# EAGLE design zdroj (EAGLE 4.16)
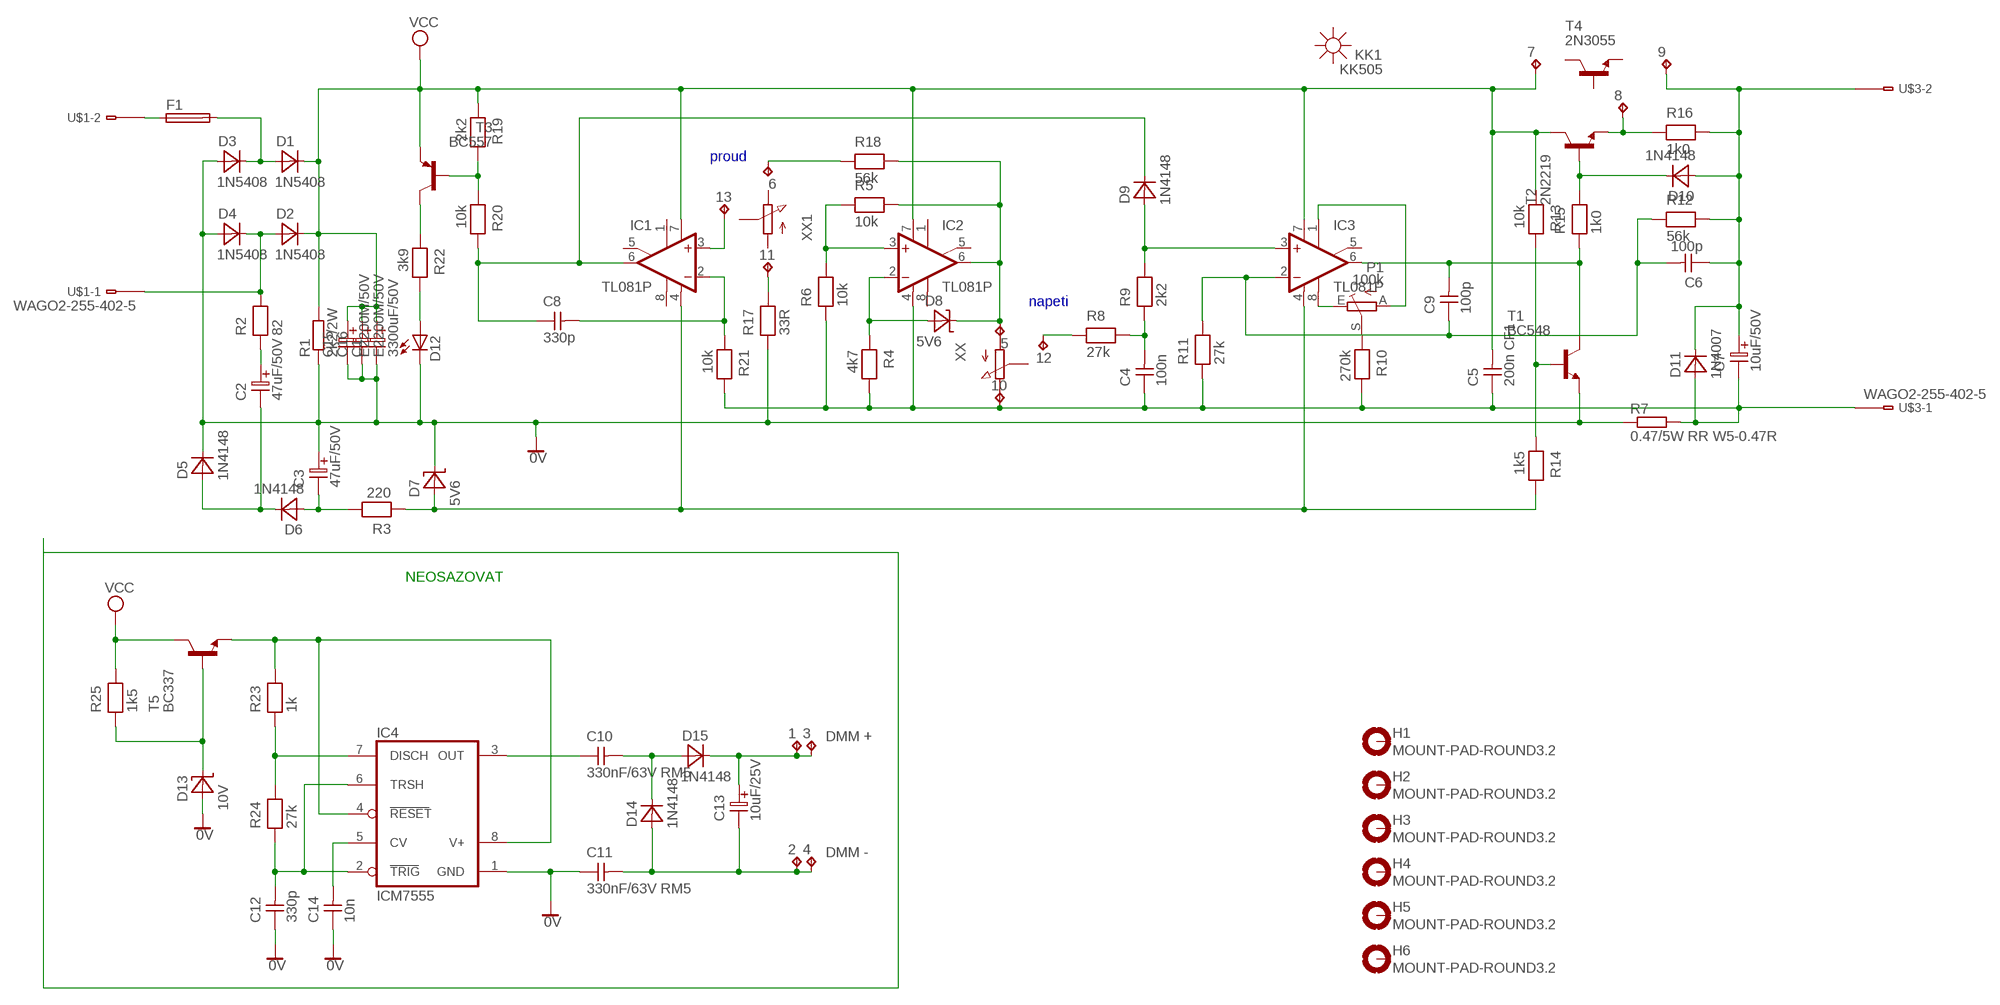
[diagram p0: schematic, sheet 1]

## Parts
1  TPPAD1-13Y  [P1-13Y]
2  TPPAD1-13Y  [P1-13Y]
3  TPPAD1-13Y  [P1-13Y]
4  TPPAD1-13Y  [P1-13Y]
5  TPPAD1-13Y  [P1-13Y]
6  TPPAD1-13Y  [P1-13Y]
7  TPPAD1-13Y  [P1-13Y]
8  TPPAD1-13Y  [P1-13Y]
9  TPPAD1-13Y  [P1-13Y]
10  TPPAD1-13Y  [P1-13Y]
11  TPPAD1-13Y  [P1-13Y]
12  TPPAD1-13Y  [P1-13Y]
13  TPPAD1-13Y  [P1-13Y]
C1  3300uF/50V  ELC-45L  [E-45L]
C2  47uF/50V  ELC-5  [ES-5]
C3  47uF/50V  ELC-5  [ES-5]
C4  100n  CAPNP-5  [C-5]
C5  200n CF1  CAPNP-5  [C-5]
C6  100p  CAPNP-5  [C-5]
C7  10uF/50V  ELC-2,5L  [ES-2,5L]
C8  330p  CAPNP-5  [C-5]
C9  100p  CAPNP-5  [C-5]
C10  330nF/63V RM5  CAPNP-5  [C-5]
C11  330nF/63V RM5  CAPNP-5  [C-5]
C12  330p  CAPNP-5  [C-5]
C13  10uF/25V  ELC-2,5L  [ES-2,5L]
C14  10n  CAPNP-5  [C-5]
C15  E2200M/50V  ELC-7,5  [ES-7,5]
C16  E2200M/50V  ELC-7,5  [ES-7,5]
D1  1N5408  DIODE-12,5  [D-12,5]
D2  1N5408  DIODE-12,5  [D-12,5]
D3  1N5408  DIODE-12,5  [D-12,5]
D4  1N5408  DIODE-12,5  [D-12,5]
D5  1N4148  DIODE-7,5  [D-7,5]
D6  1N4148  DIODE-7,5  [D-7,5]
D7  5V6  ZDIO-7,5  [D-7,5]
D8  5V6  ZDIO-7,5  [D-7,5]
D9  1N4148  DIODE-7,5  [D-7,5]
D10  1N4148  DIODE-7,5  [D-7,5]
D11  1N4007  DIODE-7,5  [D-7,5]
D12  LED3MM  [LED3MM]
D13  10V  ZDIO-7,5  [D-7,5]
D14  1N4148  DIODE-7,5  [D-7,5]
D15  1N4148  DIODE-7,5  [D-7,5]
F1  SH22,5A  [SH22,5A]
H1  MOUNT-PAD-ROUND3.2  [3,2-PAD]
H2  MOUNT-PAD-ROUND3.2  [3,2-PAD]
H3  MOUNT-PAD-ROUND3.2  [3,2-PAD]
H4  MOUNT-PAD-ROUND3.2  [3,2-PAD]
H5  MOUNT-PAD-ROUND3.2  [3,2-PAD]
H6  MOUNT-PAD-ROUND3.2  [3,2-PAD]
IC1  TL081P  [DIL08]
IC2  TL081P  [DIL08]
IC3  TL081P  [DIL08]
IC4  ICM7555  [DIL08]
KK1  KK505  [KK505]
P1  100k  TRIM_EU-CA6V  [CA6V]
R1  2k2/2W  R-EU_0414/15  [0414/15]
R2  82  RESEU-7,5  [R-7,5]
R3  220  RESEU-7,5  [R-7,5]
R4  4k7  RESEU-7,5  [R-7,5]
R5  10k  RESEU-7,5  [R-7,5]
R6  10k  RESEU-7,5  [R-7,5]
R7  0.47/5W RR W5-0.47R  R-EU_0922/22  [0922/22]
R8  27k  RESEU-7,5  [R-7,5]
R9  2k2  RESEU-7,5  [R-7,5]
R10  270k  RESEU-7,5  [R-7,5]
R11  27k  RESEU-7,5  [R-7,5]
R12  56k  RESEU-7,5  [R-7,5]
R13  10k  RESEU-7,5  [R-7,5]
R14  1k5  RESEU-7,5  [R-7,5]
R15  1k0  RESEU-7,5  [R-7,5]
R16  1k0  RESEU-7,5  [R-7,5]
R17  33R  RESEU-7,5  [R-7,5]
R18  56k  RESEU-7,5  [R-7,5]
R19  2k2  RESEU-7,5  [R-7,5]
R20  10k  RESEU-7,5  [R-7,5]
R21  10k  RESEU-7,5  [R-7,5]
R22  3k9  RESEU-7,5  [R-7,5]
R23  1k  RESEU-7,5  [R-7,5]
R24  27k  RESEU-7,5  [R-7,5]
R25  1k5  RESEU-7,5  [R-7,5]
T1  BC548  [TO92-EBC]
T2  2N2219  [TO5]
T3  BC557  [TO92-EBC]
T4  2N3055  2N2219  [TO5]
T5  BC337  BC338  [TO92-EBC]
U$1  WAGO2-255-402-5  [255-402-5]
U$3  WAGO2-255-402-5  [255-402-5]
XX  PC25  [PC25]
XX1  PC25  [PC25]

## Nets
0V: C1.2 C3.1 C11.1 C12.1 C14.1 C15.2 C16.2 D3.1(A) D4.1(A) D5.2(K) D7.2(K) D12.K(C) D13.1(A) IC4.1(GND) R1.1 R7.1 R17.1 T1.E
N$1: D2.1(A) D4.2(K) R2.2 U$1.B1(-1:B1)
N$2: D1.1(A) D3.2(K) F1.2
N$4: D13.2(K) R25.1 T5.B
N$5: F1.1 U$1.B2(-2:B1)
N$6: C3.2 D6.1(A) R3.2
N$7: D7.1(A) IC1.4(V-) IC3.4(V-) R3.1 R14.2
N$8: C2.2 D5.1(A) D6.2(K)
N$9: D12.A R22.2
N$10: C2.1 R2.1
N$11: C14.2 IC4.5(CV)
N$12: R22.1 T3.C
N$13: R19.2 R20.1 T3.B
N$14: C8.1 D9.2(K) IC1.6(OUT) R20.2
N$15: C8.2 IC1.2(-IN) R21.1
N$16: 8.1(TP) R16.1 T2.1(E)
N$17: 13.1(TP) IC1.3(+IN)
N$18: 6.1(TP) R18.1
N$19: 5.1(TP) D8.2(K) IC2.6(OUT) R5.2 R18.2
N$20: 11.1(TP) R17.2
N$21: D8.1(A) IC2.2(-IN) R4.1
N$22: IC2.3(+IN) R5.1 R6.2
N$23: 12.1(TP) R8.1
N$24: C4.2 R8.2 R9.1
N$25: D9.1(A) IC3.3(+IN) R9.2
N$26: C6.2 C9.1 IC3.2(-IN) R11.2 R12.1
N$27: IC3.1(ON1) P1.A
N$28: IC3.8(OPT) P1.E
N$29: P1.S R10.1
N$30: C9.2 IC3.6(OUT) R15.1 T1.C
N$31: R13.2 R14.1 T1.B
N$32: D10.2(K) R15.2 T2.2(B)
N$33: C10.1 IC4.3(OUT)
N$35: 9.1(TP) C6.1 C7.1 D10.1(A) D11.2(K) R12.2 R16.2 U$3.B2(-2:B1)
N$36: IC4.4(RESET) IC4.8(V+) R23.2 T5.E
N$37: IC4.7(DISCH) R23.1 R24.2
N$38: C12.2 IC4.2(TRIG) IC4.6(TRSH) R24.1
N$39: 1.1(TP) 3.1(TP) C13.1 D15.2(K)
N$40: 2.1(TP) 4.1(TP) C11.2 C13.2 D14.1(A)
N$41: C10.2 D14.2(K) D15.1(A)
N$43: 10.1(TP) C4.1 C5.1 C7.2 D11.1(A) IC2.4(V-) R4.2 R6.1 R7.2 R10.2 R11.1 R21.2 U$3.B1(-1:B1)
VCC: 7.1(TP) C1.1 C5.2 C15.1 C16.1 D1.2(K) D2.2(K) IC1.7(V+) IC2.7(V+) IC3.7(V+) R1.2 R13.1 R19.1 R25.2 T2.3(C) T3.E T5.C
Unconnected: H1.B3,2(MOUNT) H2.B3,2(MOUNT) H3.B3,2(MOUNT) H4.B3,2(MOUNT) H5.B3,2(MOUNT) H6.B3,2(MOUNT) IC1.1(ON1) IC1.5(ON2) IC1.8(OPT) IC2.1(ON1) IC2.5(ON2) IC2.8(OPT) IC3.5(ON2) T4.1(E) T4.2(B) T4.3(C) U$1.A1(-1:A1) U$1.A2(-2:A1) U$3.A1(-1:A1) U$3.A2(-2:A1) XX1.A XX1.E XX1.S XX.A XX.E XX.S

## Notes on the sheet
- proud
- napeti
- NEOSAZOVAT
- DMM +
- DMM -

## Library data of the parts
1-13 = testpad:TP
C1 = discrete:ELC-45L
C2 C3 = discrete:ELC-5
C4-C6 C8-C12 C14 = discrete:CAPNP-5
C7 C13 = discrete:ELC-2,5L
C15 C16 = discrete:ELC-7,5
D1-D4 = discrete:DIODE-12,5
D5 D6 D9-D11 D14 D15 = discrete:DIODE-7,5
D7 D8 D13 = discrete:ZDIO-7,5
D12 = led:LED: LED
F1 = fuse:SH22,5A: FUSE HOLDER
H1-H6 = holes:MOUNT-PAD-ROUND: MOUNTING PAD, round
IC1-IC3 = linear:TL081: OP AMP
IC4 = maxim:ICM7555: TIMER
KK1 = heatsink:KK505: HEATSINK
P1 = pot:TRIM_EU-: POTENTIOMETER
R1 R7 = rcl:R-EU_: RESISTOR, European symbol
R2-R6 R8-R25 = discrete:RESEU-7,5
T1 = transistor-npn:BC548*: NPN Transistor
T2 T4 = transistor-npn:2N2219: NPN Transistor
T3 = transistor-pnp:BC557*: PNP Transistror
T5 = transistor-npn:BC338*: NPN Transistor
U$1 U$3 = con-wago:WAGO2-: WAGO Cage Clamp
XX XX1 = pot-vitrohm:PC25: VITROHM POTENTIOMETER

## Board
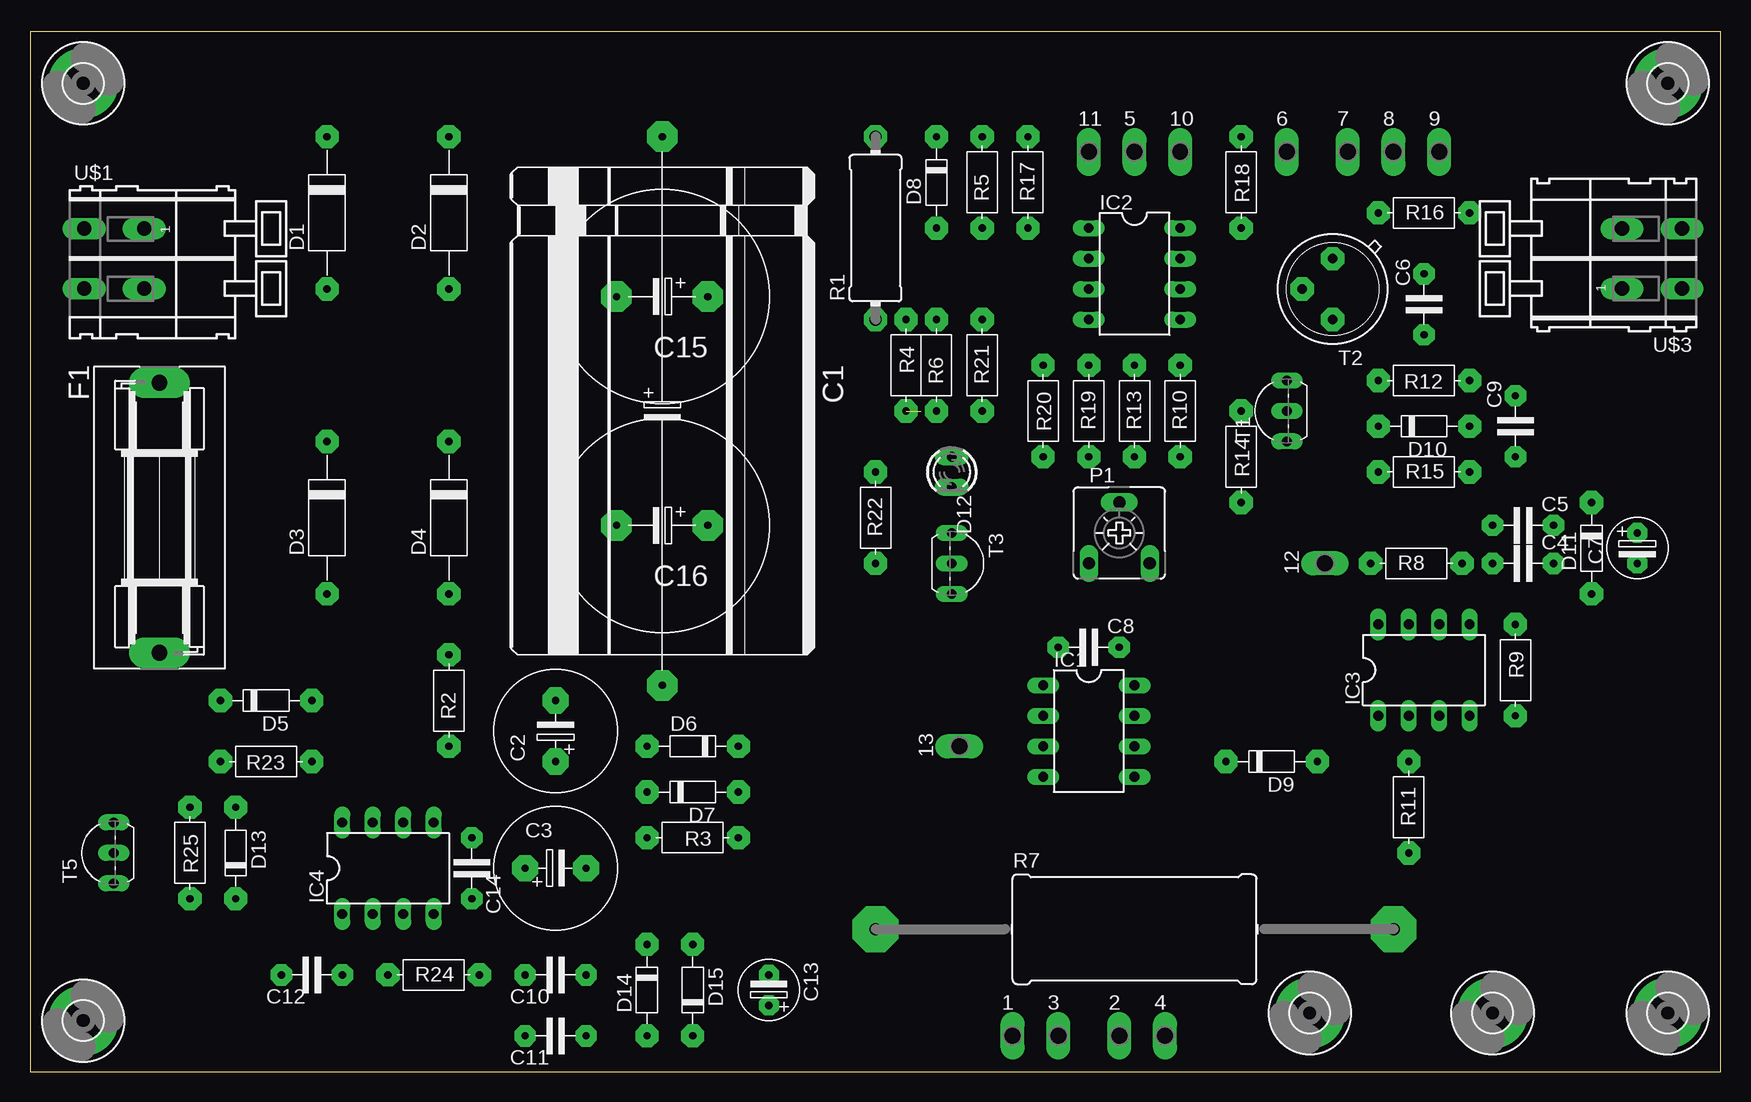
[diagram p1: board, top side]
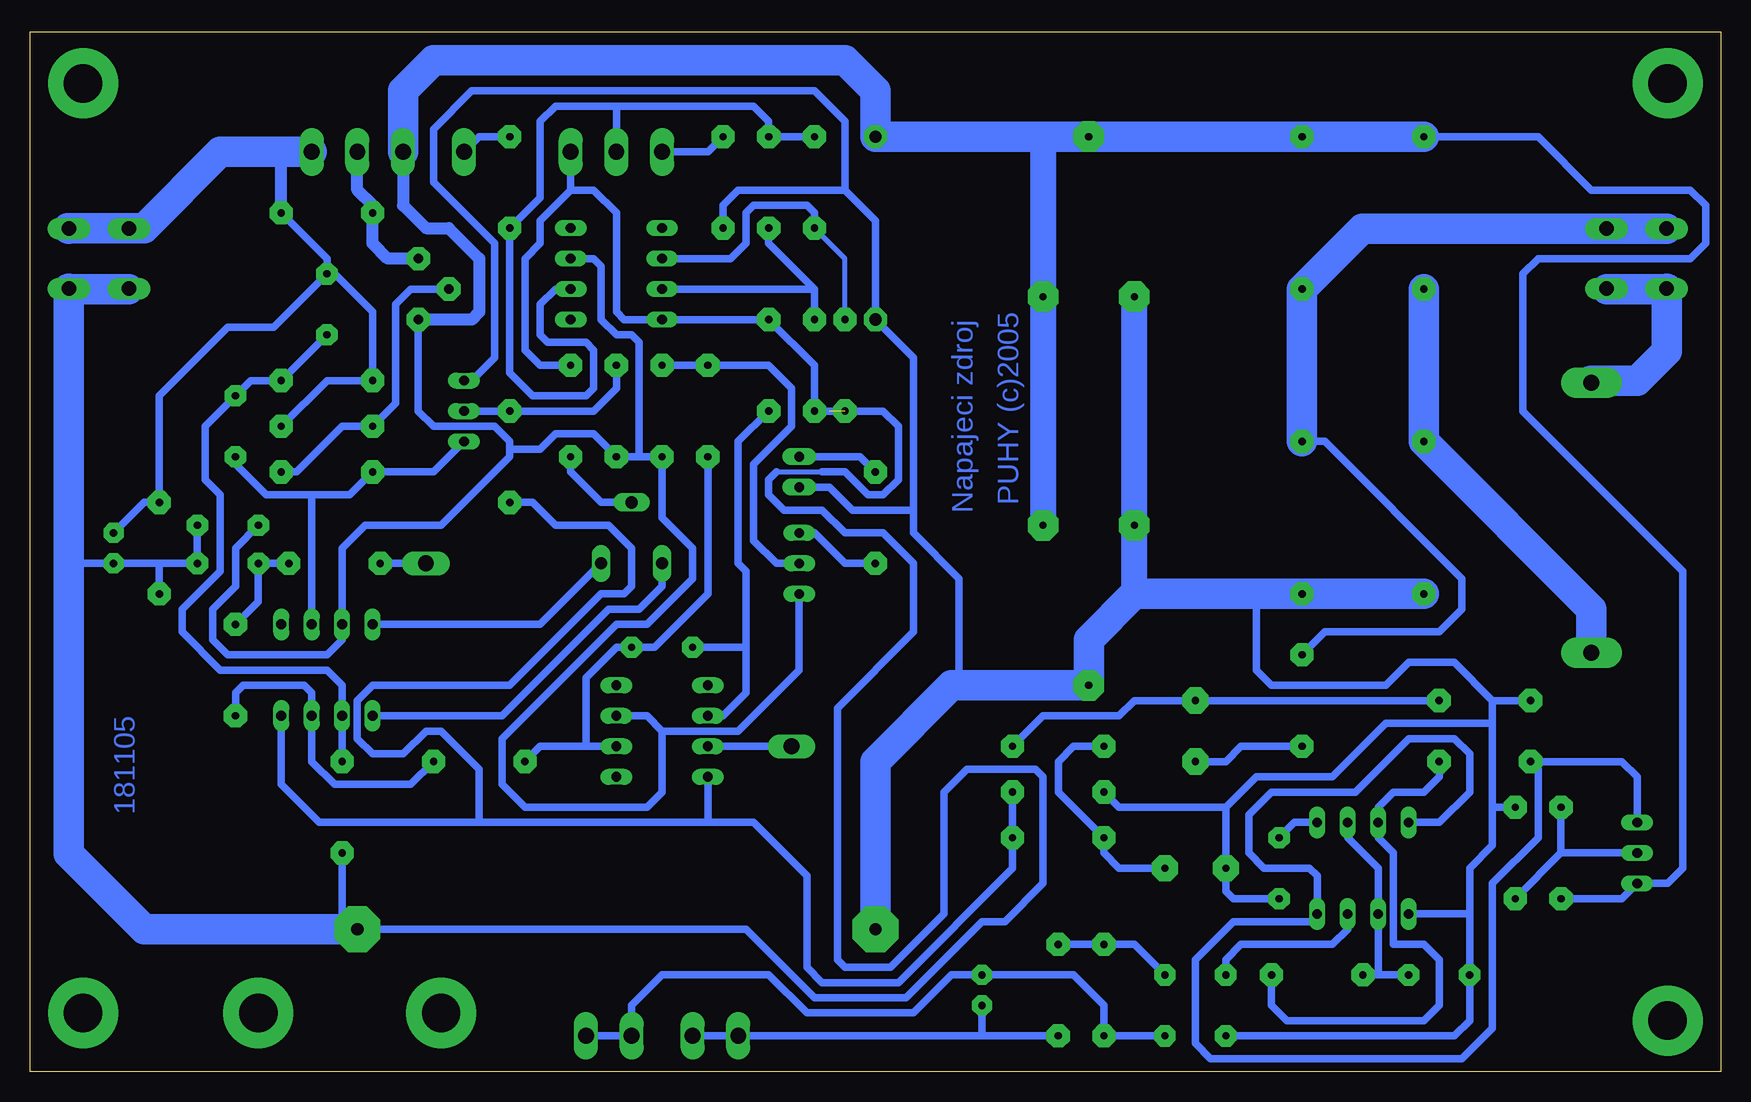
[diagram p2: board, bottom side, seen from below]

Size 140.95 x 86.67 mm. Coordinates in mm from the lower left corner, seen from the top.
Outline: 0,0 140.95,0 140.95,86.67 0,86.67 0,0
Copper layers (1*16): Top 0.035mm / dielectric 1.5mm / Bottom 0.035mm
Design rules "default": minimum track width 10mil, minimum drill 24mil, track to track 8mil, track to pad 8mil, pad to pad 8mil, via to via 8mil, smd to smd 8mil, copper to edge 40mil, drill to drill 8mil, minimum pad ring 10mil, minimum via ring 8mil, stop-mask expansion 4mil, vias tented up to drill 0mil, thermal gap 10mil

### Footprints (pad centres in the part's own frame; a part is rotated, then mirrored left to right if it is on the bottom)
P1-13Y = drill 1.321 pad 1.905 long: 1 0,0
E-45L = drill 0.61 pad 2.54 octagon: 1 0,0; 2 45.72,0
ES-5 = drill 0.61 pad 2.184 octagon: 1 -2.54,0; 2 2.54,0
C-5 = drill 0.61 pad 1.778 octagon: 1 -2.54,0; 2 2.54,0
ES-2,5L = drill 0.61 pad 1.676 octagon: 1 0,0; 2 2.54,0
ES-7,5 = drill 0.61 pad 2.54 octagon: 1 -3.81,0; 2 3.81,0
D-12,5 = drill 0.61 pad 1.93 octagon: 1 -6.35,0; 2 6.35,0
D-7,5 = drill 0.61 pad 1.93 octagon: 1 -3.81,0; 2 3.81,0
LED3MM = drill 0.813 pad 1.422 long: A -1.27,0; K 1.27,0
SH22,5A = drill 1.321 pad 2.54 long: 1 -11.252,0; 2 11.252,0
3,2-PAD = drill 3.2 pad 5.842 round: B3,2 0,0
DIL08 = drill 0.813 long: 1 -3.81,-3.81; 2 -1.27,-3.81; 3 1.27,-3.81; 4 3.81,-3.81; 5 3.81,3.81; 6 1.27,3.81; 7 -1.27,3.81; 8 -3.81,3.81
CA6V = drill 1.016 long: A -2.54,-2.54; E 2.54,-2.54; S 0,2.54
0414/15 = drill 1.016 pad 1.93 octagon: 1 -7.62,0; 2 7.62,0
R-7,5 = drill 0.61 pad 1.93 octagon: 1 -3.81,0; 2 3.81,0
0922/22 = drill 1.016 pad 3.81 octagon: 1 -21.59,0; 2 21.59,0
TO92-EBC = drill 0.813 long: B 0,-1.27; C -2.54,-1.27; E 2.54,-1.27
TO5 = drill 0.813 pad 1.93 octagon: 1 0,-2.54; 2 2.54,0; 3 0,2.54
255-402-5 = drill 1.2 long: A1 -2.5,0; A2 2.5,0; B1 -2.5,-5; B2 2.5,-5
PC25 = smd 2.2 x 0.8: 4 0,1.65 | smd 0.9 x 1.4: A -1.35,-1.9; E 1.35,-1.9; S 0,-1.9

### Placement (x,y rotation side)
1  81.91,3.01 0 top
2  90.8,3.01 0 top
3  85.72,3.01 0 top
4  94.61,3.01 0 top
5  92.07,76.67 0 top
6  104.77,76.67 0 top
7  109.85,76.67 0 top
8  113.66,76.67 0 top
9  117.47,76.67 0 top
10  95.88,76.67 0 top
11  88.26,76.67 0 top
12  107.94,42.38 90 top
13  77.47,27.14 90 top
C1  52.7,77.94 270 top
C2  43.81,28.41 90 top
C3  43.81,16.98 0 top
C4  124.46,42.38 180 top
C5  124.46,45.56 180 top
C6  116.2,63.97 270 top
C7  133.98,44.92 270 top
C8  88.26,35.39 180 top
C9  123.82,53.81 270 top
C10  43.81,8.09 0 top
C11  43.81,3.01 0 top
C12  23.49,8.09 0 top
C13  61.59,5.55 90 top
C14  36.83,16.98 90 top
C15  52.7,64.61 180 top
C16  52.7,45.56 180 top
D1  24.76,71.59 90 top
D2  34.92,71.59 90 top
D3  24.76,46.19 90 top
D4  34.92,46.19 90 top
D5  19.68,30.95 180 top
D6  55.24,27.14 0 top
D7  55.24,23.33 180 top
D8  75.56,74.13 90 top
D9  103.5,25.87 180 top
D10  116.2,53.81 180 top
D11  130.17,43.65 90 top
D12  76.83,50 270 top
D13  17.14,18.25 270 top
D14  51.43,6.82 90 top
D15  55.24,6.82 270 top
F1  10.79,46.19 270 top
H1  4.44,82.39 0 top
H2  4.44,4.28 0 top
H3  121.91,4.91 0 top
H4  136.52,4.91 0 top
H5  106.68,4.91 0 top
H6  136.52,82.39 0 top
IC1  88.26,28.41 270 top
IC2  92.07,66.51 270 top
IC3  116.2,33.49 0 top
IC4  29.84,16.98 0 top
KK1  not placed on the board
P1  90.8,44.92 0 top
R1  70.48,70.32 90 top
R2  34.92,30.95 90 top
R3  55.24,19.52 180 top
R4  73.02,58.89 270 top
R5  79.37,74.13 90 top
R6  75.56,58.89 90 top
R7  92.07,11.9 0 top
R8  115.56,42.38 0 top
R9  123.82,33.49 270 top
R10  95.88,55.08 90 top
R11  114.93,22.06 90 top
R12  116.2,57.62 180 top
R13  92.07,55.08 90 top
R14  100.96,51.27 270 top
R15  116.2,50 0 top
R16  116.2,71.59 0 top
R17  83.18,74.13 90 top
R18  100.96,74.13 270 top
R19  88.26,55.08 90 top
R20  84.45,55.08 270 top
R21  79.37,58.89 90 top
R22  70.48,46.19 90 top
R23  19.68,25.87 180 top
R24  33.65,8.09 0 top
R25  13.33,18.25 270 top
T1  103.5,55.08 90 top
T2  108.58,65.24 180 top
T3  78.1,42.38 270 top
T4  not placed on the board
T5  5.71,18.25 90 top
U$1  9.52,67.78 270 top
U$3  132.71,67.78 90 top
XX  not placed on the board
XX1  not placed on the board

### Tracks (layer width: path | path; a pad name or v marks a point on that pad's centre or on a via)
0V
  Bottom 0.61: 20.95,13.17 C12.1 20.95,4.28 22.22,3.01 C11.1 | 20.95,13.17 IC4.1 | 41.27,22.06 38.73,24.6 32.38,24.6 27.94,29.04 19.04,29.04 | 41.27,22.06 50.16,22.06 D7.2 | 20.95,13.17 20.95,16.98 19.04,18.89 19.04,22.06 | 19.04,22.06 D13.1 | 19.04,22.06 19.04,29.04 | C14.1 40.63,14.44 41.27,15.07 C3.1 41.27,22.06 | 73.02,73.5 81.91,73.5 83.18,72.23 R17.1 | 67.31,46.83 67.31,44.92 63.49,41.11 63.49,32.22 | 67.31,46.83 67.31,59.53 R1.1 70.48,70.95 73.02,73.5 | T1.E 104.13,57.62 102.23,59.53 102.23,69.05 107.31,74.13 107.31,78.58 104.13,81.75 75.56,81.75 73.02,79.21 73.02,73.5 | 67.31,46.83 72.38,46.83 74.29,48.73 D12.K | 38.73,39.84 38.73,33.49 37.46,32.22 27.94,32.22 26.03,34.12 22.22,34.12 19.04,30.95 | 19.04,29.04 19.04,30.95 | 19.04,30.95 D5.2
  Bottom 2.184: C15.2 C16.2 48.89,39.84
  Bottom 2.54: R7.1 70.48,25.87 64.13,32.22 63.49,32.22 62.23,32.22 | D3.1 D4.1 38.73,39.84 48.89,39.84 52.7,36.03 C1.2 | C1.2 52.7,33.49 | C1.2 62.23,32.22 | 62.23,32.22 62.86,32.22
N$1
  Bottom 0.61: R2.2 33.02,36.67 23.49,36.67 21.59,38.57 21.59,41.11 33.02,52.54 D4.2
  Bottom 2.54: U$1.B1 29.88,70.28 D2.1 D4.2
N$2
  Bottom 2.54: D1.1 D3.2 10.79,38.57 F1.2
N$3
  Bottom 2.54: 132.71,65.24 137.79,65.24
N$4
  Bottom 0.61: 13.33,18.25 D13.2 | 13.33,18.25 R25.1 | T5.B 13.33,18.25
N$5
  Bottom 2.54: U$1.B2 4.52,60.08 6.98,57.62 10.79,57.62 F1.1
N$6
  Bottom 0.61: D6.1 53.97,27.14 55.24,25.87 55.24,23.33 R3.2 51.43,18.25 50.16,16.98 C3.2
N$7
  Bottom 0.61: IC3.4 120.01,23.96 116.84,20.79 103.5,20.79 | 84.45,20.79 80.64,20.79 76.19,16.34 76.19,8.73 74.92,7.46 68.58,7.46 59.05,16.98 R3.1 D7.1 | 84.45,20.79 103.5,20.79 | 84.45,20.79 IC1.4 | 103.5,20.79 103.5,25.24 106.68,28.41 107.94,28.41 109.85,26.5 112.39,26.5 113.66,27.78 113.66,30.95 112.39,32.22 100.96,32.22 93.34,39.84 91.44,39.84 90.8,40.47 90.8,43.65 92.71,45.56 97.15,45.56 99.06,47.46 R14.2
N$8
  Bottom 0.61: D5.1 C2.2 48.89,30.95 50.16,29.68 56.51,29.68 D6.2
N$9
  Bottom 0.61: R22.2 71.75,51.27 D12.A
N$10
  Bottom 0.61: R2.1 40,27.14 41.27,25.87 C2.1
N$11
  Bottom 0.61: C14.2 35.55,20.79 IC4.5
N$12
  Bottom 0.61: R22.1 73.02,42.38 75.56,44.92 T3.C
N$13
  Bottom 0.61: T3.B 78.73,42.38 80.64,44.28 80.64,50.64 77.47,53.81 77.47,56.98 79.37,58.89 R20.1 R19.2
N$14
  Bottom 0.61: D9.2 98.42,27.14 94.61,27.14 | IC1.6 94.61,27.14 | 94.61,27.14 94.61,32.86 92.07,35.39 C8.1 88.9,35.39 84.45,39.84 R20.2
N$15
  Bottom 0.61: IC1.2 83.18,29.68 81.28,31.58 81.28,35.39 | 81.28,35.39 C8.2 | R21.1 81.91,52.54 81.91,42.38 81.28,41.75 81.28,35.39
N$16
  Bottom 1.016: T2.1 111.12,67.78 112.39,69.05 R16.1 112.39,72.23 113.66,73.5 8.1
N$17
  Bottom 0.61: 13.1 IC1.3
N$18
  Bottom 0.61: R18.1 103.5,77.94 6.1
N$19
  Bottom 0.61: D8.2 R5.2 79.37,79.21 80.64,80.48 92.07,80.48 | 92.07,80.48 97.15,80.48 98.42,79.21 98.42,72.86 R18.2 100.96,58.26 99.06,56.35 94.61,56.35 93.97,56.98 93.97,60.16 94.61,60.8 97.78,60.8 98.42,61.43 98.42,63.97 97.15,65.24 IC2.6 | 92.07,80.48 5.1
N$20
  Bottom 0.61: 11.1 84.45,76.67 R17.2
N$21
  Bottom 0.406: R4.1 73.02,67.78 D8.1
  Bottom 0.61: D8.1 75.56,71.59 76.19,72.23 80.64,72.23 81.28,71.59 81.28,69.05 82.55,67.78 IC2.2
N$22
  Bottom 0.61: R6.2 75.56,65.24 | 75.56,65.24 IC2.3 | 75.56,65.24 79.37,69.05 R5.1
N$23
  Bottom 0.61: 12.1 R8.1
N$24
  Bottom 0.61: R9.1 121.91,39.2 C4.2 R8.2
N$25
  Bottom 0.61: D9.1 109.22,23.96 115.56,23.96 117.47,25.87 IC3.3 117.47,31.58 118.1,32.22 123.19,32.22 123.82,31.58 R9.2
N$26
  Bottom 0.61: C6.2 R12.1 122.55,57.62 C9.1 126.36,53.81 126.36,49.37 125.09,48.09 125.09,41.75 128.26,38.57 128.26,36.67 125.09,33.49 116.2,33.49 114.93,32.22 IC3.2 R11.2
N$27
  Bottom 0.61: 111.75,29.68 IC3.1 101.59,29.68 92.71,38.57 90.16,38.57 88.26,40.47 P1.A
N$28
  Bottom 0.61: P1.E 98.42,37.3 IC3.8
N$29
  Bottom 0.61: P1.S 93.34,47.46 95.88,50 R10.1
N$30
  Bottom 0.61: T1.C 107.31,50 R15.1 114.29,48.09 117.47,48.09 | 117.47,48.09 121.28,48.09 123.82,50.64 C9.2 | IC3.6 117.47,48.09
N$31
  Bottom 0.61: R13.2 92.07,56.98 93.97,55.08 T1.B R14.1
N$32
  Bottom 0.61: T2.2 109.22,65.24 110.49,63.97 110.49,55.72 D10.2 114.93,53.81 118.74,50 R15.2
N$33
  Bottom 0.61: IC4.3 31.11,11.9 32.38,10.63 40,10.63 41.27,9.36 C10.1
N$35
  Bottom 0.61: R16.2 116.2,67.78 C6.1 | C6.1 120.65,62.06 124.46,62.06 130.17,56.35 D11.2 131.44,47.46 C7.1 | D10.1 116.2,57.62 R12.2 112.39,63.34 115.56,66.51 C6.1
  Bottom 1.016: R16.2 120.01,76.67
  Bottom 2.54: 9.1 120.01,76.67 125.09,76.67 131.44,70.32 137.75,70.32 | 137.75,70.32 137.79,70.32 | 137.75,70.32 U$3.B2
N$36
  Bottom 0.61: IC4.8 23.49,20.79 20.95,23.33 20.95,26.5 22.22,27.78 26.03,27.78 30.48,23.33 37.46,23.33 39.36,21.43 39.36,18.25 38.09,16.98 34.28,16.98 33.65,16.34 IC4.4 33.65,12.54 40.63,12.54 43.81,9.36 43.81,2.38 42.54,1.11 21.59,1.11 19.04,3.64 19.04,15.71 15.23,19.52 15.23,25.24 R23.2 8.25,25.87 6.98,24.6 T5.E
N$37
  Bottom 0.61: R24.2 37.46,5.55 36.19,4.28 24.76,4.28 23.49,5.55 23.49,9.36 24.76,10.63 27.3,10.63 27.3,18.25 28.57,19.52 IC4.7 28.57,22.06 27.3,23.33 24.76,23.33 23.49,24.6 R23.1
N$38
  Bottom 0.61: C12.2 28.57,8.09 | 28.57,8.09 R24.1 | 28.57,8.09 IC4.2 28.57,16.98 31.11,19.52 IC4.6
N$39
  Bottom 0.61: D15.2 61.59,3.01 | 61.59,3.01 1.1 3.1 | 61.59,3.01 C13.1
N$40
  Bottom 0.61: C11.2 D14.1 51.43,5.55 53.97,8.09 C13.2 64.13,8.09 67.31,4.91 76.19,4.91 79.37,8.09 88.26,8.09 90.8,5.55 2.1 4.1
N$41
  Bottom 0.61: C10.2 48.89,10.63 D14.2 D15.1
N$42
  Bottom 2.54: 4.44,65.24 9.52,65.24
N$43  (1 unrouted)
  Bottom 0.406: 78.73,50 74.92,50 | 74.29,55.08 R6.1
  Bottom 0.61: 74.92,55.08 74.29,55.08 69.84,55.08 68.58,53.81 68.58,49.37 69.84,48.09 71.12,48.09 73.02,50 74.92,50 | 78.73,50 79.37,49.37 79.37,48.09 78.1,46.83 74.92,46.83 73.02,44.92 69.84,44.92 67.31,42.38 67.31,36.67 73.66,30.32 73.66,9.36 73.02,8.73 69.21,8.73 64.77,13.17 64.77,23.33 62.86,25.24 57.15,25.24 56.51,24.6 56.51,15.71 59.69,12.54 61.59,12.54 67.94,6.18 75.56,6.18 81.28,11.9 R7.2 | R6.1 75.56,58.89 R21.2 IC2.4 91.44,62.7 92.07,63.34 92.07,71.59 93.97,73.5 95.88,73.5 | 95.88,75.4 10.1 95.88,73.5 | 137.79,32.22 137.71,42.38 C7.2 130.17,42.38 | R10.2 98.42,58.89 99.69,60.16 99.69,67.78 98.42,69.05 98.42,70.95 95.88,73.5 | 114.93,11.9 R11.1 | 130.17,42.38 D11.1 | 130.17,42.38 C4.1 C5.1
  Bottom 2.54: U$3.B1 137.71,42.38 137.71,18.17 131.44,11.9 114.93,11.9 R7.2
VCC
  Bottom 0.61: R25.2 8.25,14.44 T5.C 4.44,15.71 3.17,16.98 3.17,41.75 16.5,55.08 16.5,66.51 15.23,67.78 2.54,67.78 1.27,69.05 1.27,72.23 2.54,73.5 10.79,73.5 15.23,77.94 D1.2 25.39,77.94 | IC2.7 93.97,67.78 93.34,67.15 93.34,62.7 92.07,61.43 90.8,61.43 90.16,60.8 90.16,51.27 | 90.16,51.27 R19.1 88.26,46.19 85.72,43.65 85.72,41.11 89.53,37.3 92.07,37.3 101.59,27.78 101.59,23.96 99.69,22.06 89.53,22.06 88.26,23.33 88.26,28.41 | 90.16,51.27 R13.1 93.97,53.17 97.15,53.17 98.42,51.91 100.96,51.91 | IC1.7 89.53,29.68 88.26,28.41 | 88.26,28.41 81.91,28.41 76.83,33.49 T3.E | T2.3 108.58,55.08 107.31,53.81 102.23,53.81 100.96,52.54 100.96,51.91 | 100.96,51.91 100.96,51.27 106.68,45.56 113.03,45.56 114.93,43.65 IC3.7 114.93,36.03 116.2,34.76 124.46,34.76 125.72,36.03 125.72,38.57 123.82,40.47 123.82,43.65 C5.2
  Bottom 1.016: 7.1 109.85,72.23 107.94,70.32 106.04,70.32 103.5,67.78 103.5,63.34 104.13,62.7 T2.3
  Bottom 2.184: 56.51,77.94 C15.1 C16.1
  Bottom 2.54: 7.1 109.85,81.75 107.31,84.29 73.02,84.29 70.48,81.75 R1.2 56.51,77.94 C1.1 D2.2 D1.2

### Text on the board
Bottom: PUHY (c)2005 | Napajeci zdroj | 181105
